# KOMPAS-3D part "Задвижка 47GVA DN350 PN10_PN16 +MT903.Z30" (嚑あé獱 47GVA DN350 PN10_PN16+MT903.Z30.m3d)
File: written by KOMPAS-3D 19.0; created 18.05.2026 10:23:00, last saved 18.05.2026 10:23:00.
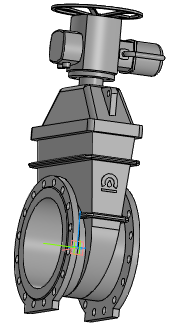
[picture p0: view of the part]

Document properties: Автор: Энергия; Полное имя файла: ..\Задвижка 47GVA DN50_DN1000+MT903.Z\Задвижка 47GVA DN350 PN10_PN16+MT903.Z30.a3d

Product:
- Part/product: Задвижка 47GVA DN350 PN10_PN16 +MT903.Z30
    Масса: 479.551
  - Body: Электропривод MT903.Z20-30
      Масса: 83.2154
  - Body: Задвижка 47GV DN350 PN10_PN16 с маховиком
      Масса: 396.335

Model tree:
1. Операция без истории:1
2. Операция без истории:2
